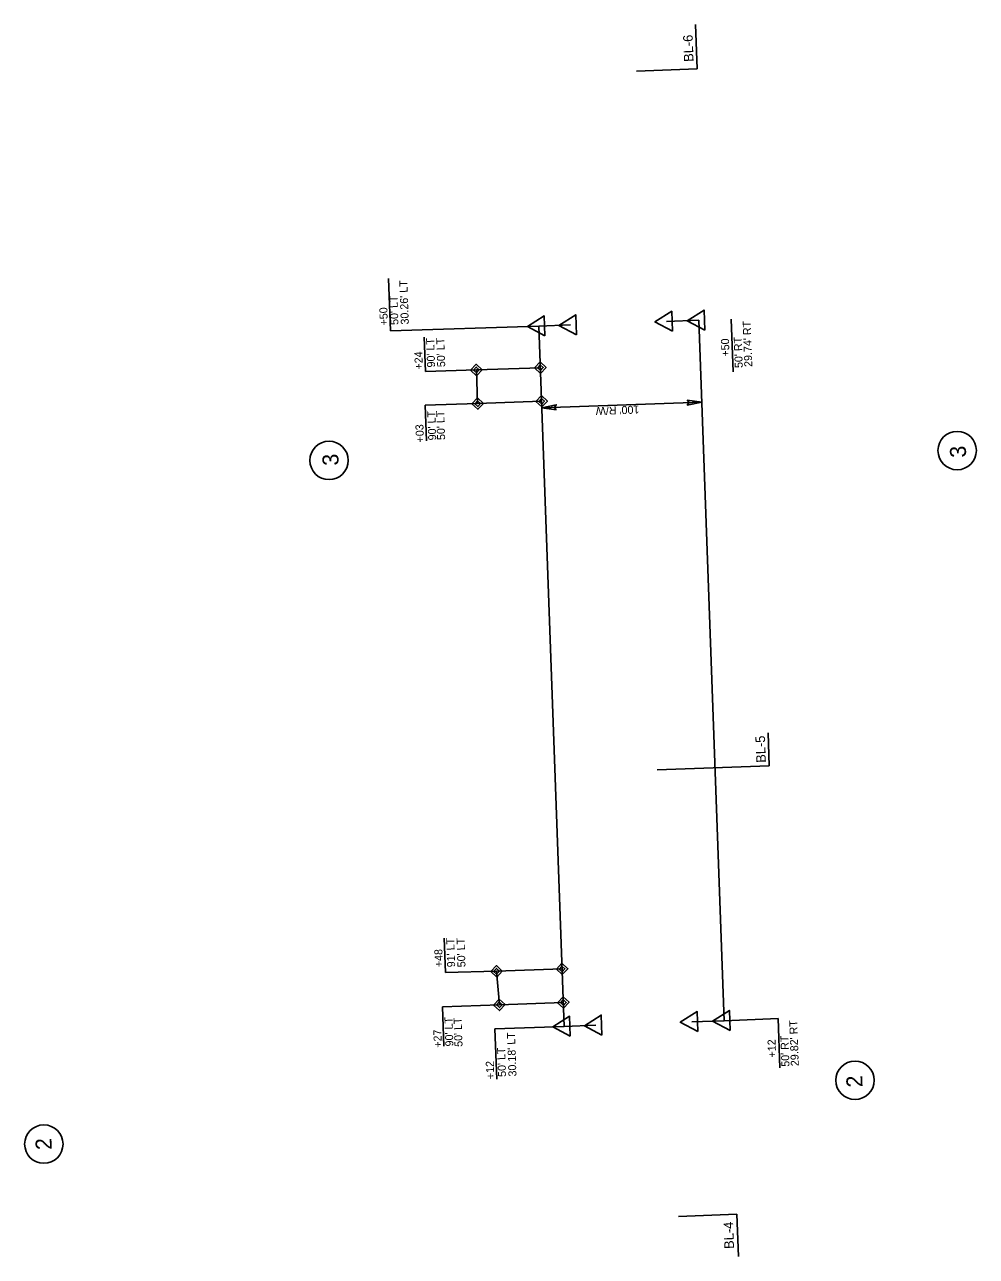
# Model space of a CAD drawing. Extents: x 2065634 to 2066229, y 144790 to 146885.
# Drawn here: x 2065634 to 2066229, y 146115 to 146885 of the extents above; entities that cross this region are included whole.
import ezdxf

# ---------------------------------------------------------------- set-up
doc = ezdxf.new("R2010")
doc.units = 0
for name, color, linetype in [('Prop Dimension', 7, 'Continuous'), ('Prop DSN Text', 7, 'Continuous'), ('Prop Easement Permanent Utility', 7, 'Continuous'), ('Prop Easement Permanent Utility Station Offsets', 7, 'Continuous'), ('Prop Parcel Number CELL', 7, 'Continuous'), ('Prop Parcel Number Text', 7, 'Continuous'), ('Prop ROW Marker CELL', 7, 'Continuous'), ('Prop ROW Permanent Easement CELL', 7, 'Continuous'), ('Prop ROW RW Lines', 7, 'Continuous'), ('Prop ROW Station Offsets', 7, 'Continuous'), ('Prop Terminator CELL', 7, 'Continuous')]:
    doc.layers.add(name, color=color, linetype=linetype)

msp = doc.modelspace()

# ---------------------------------------------------------------- linework, layer by layer
at = {"layer": 'Prop Dimension'}
msp.add_line((2065956.94, 146645), (2066056.88, 146648.61), dxfattribs=at)
at = {"layer": 'Prop DSN Text'}
for p, q in [((2066054.02, 146856.81), (2066053.02, 146884.51)), ((2066016.15, 146855.44), (2066054.02, 146856.81)), ((2066099.13, 146421.28), (2066098.39, 146441.8)), ((2066029.08, 146418.75), (2066099.13, 146421.28)), ((2066042.47, 146139.68), (2066078.89, 146141)), ((2066078.89, 146141), (2066079.84, 146114.71))]:
    msp.add_line(p, q, dxfattribs=at)
at = {"layer": 'Prop Easement Permanent Utility'}
for p, q in [((2065916.06, 146668.68), (2065956.03, 146670.12)), ((2065916.82, 146647.69), (2065916.06, 146668.68)), ((2065916.82, 146647.69), (2065956.79, 146649.13)), ((2065928.64, 146292.88), (2065969.62, 146294.37)), ((2065930.4, 146271.93), (2065928.64, 146292.88)), ((2065930.4, 146271.93), (2065970.38, 146273.38))]:
    msp.add_line(p, q, dxfattribs=at)
at = {"layer": 'Prop Easement Permanent Utility Station Offsets'}
for p, q in [((2065883.39, 146689.17), (2065884.16, 146667.7)), ((2065916.06, 146668.68), (2065884.16, 146667.7)), ((2065916.82, 146647.69), (2065884.01, 146646.66)), ((2065884.01, 146646.66), (2065884.81, 146624.31)), ((2065895.94, 146313.61), (2065896.72, 146292.05)), ((2065928.64, 146292.88), (2065896.72, 146292.05)), ((2065930.4, 146271.93), (2065894.89, 146270.7)), ((2065894.89, 146270.7), (2065895.78, 146246))]:
    msp.add_line(p, q, dxfattribs=at)
at = {"layer": 'Prop Parcel Number CELL'}
for p, q in [((2066216.55, 146618.33), (2066216.55, 146618.33)), ((2065823.94, 146612.14), (2065823.94, 146612.14)), ((2066152.7, 146224.75), (2066152.7, 146224.75)), ((2065645.68, 146184.86), (2065645.68, 146184.86))]:
    msp.add_line(p, q, dxfattribs=at)
for centre in [(2065823.94, 146612.14), (2066216.55, 146618.33), (2066152.7, 146224.75), (2065645.68, 146184.86)]:
    msp.add_circle(centre, 12, dxfattribs=at)
at = {"layer": 'Prop ROW Marker CELL'}
for p, q in [((2065955.09, 146696.1), (2065955.09, 146696.1)), ((2065974.82, 146696.82), (2065974.82, 146696.82)), ((2066034.78, 146698.98), (2066034.78, 146698.98)), ((2066055.03, 146699.72), (2066055.03, 146699.72)), ((2065970.92, 146258.39), (2065970.92, 146258.39)), ((2065990.72, 146259.11), (2065990.72, 146259.11)), ((2066050.68, 146261.27), (2066050.68, 146261.27)), ((2066070.85, 146262), (2066070.85, 146262))]:
    msp.add_line(p, q, dxfattribs=at)
for points in [[(2065958.92, 146689.99), (2065947.9, 146695.84), (2065958.47, 146702.48)], [(2065978.65, 146690.7), (2065967.63, 146696.56), (2065978.19, 146703.19)], [(2066038.61, 146692.87), (2066027.59, 146698.72), (2066038.15, 146705.36)], [(2066058.85, 146693.6), (2066047.83, 146699.46), (2066058.4, 146706.09)], [(2065974.74, 146252.27), (2065963.72, 146258.13), (2065974.29, 146264.77)], [(2065994.55, 146252.99), (2065983.53, 146258.85), (2065994.09, 146265.48)], [(2066054.51, 146255.16), (2066043.49, 146261.01), (2066054.06, 146267.65)], [(2066074.68, 146255.89), (2066063.66, 146261.74), (2066074.22, 146268.38)]]:
    msp.add_lwpolyline(points, close=True, dxfattribs=at)
at = {"layer": 'Prop ROW Permanent Easement CELL'}
for p, q in [((2065916.06, 146668.68), (2065916.06, 146668.68)), ((2065956.03, 146670.12), (2065956.03, 146670.12)), ((2065916.82, 146647.69), (2065916.82, 146647.69)), ((2065956.79, 146649.13), (2065956.79, 146649.13)), ((2065969.62, 146294.37), (2065969.62, 146294.37)), ((2065928.64, 146292.88), (2065928.64, 146292.88)), ((2065930.4, 146271.93), (2065930.4, 146271.93)), ((2065970.38, 146273.38), (2065970.38, 146273.38))]:
    msp.add_line(p, q, dxfattribs=at)
for points in [[(2065919.66, 146668.81), (2065916.19, 146665.08), (2065912.46, 146668.55), (2065915.93, 146672.27)], [(2065917.86, 146668.74), (2065916.12, 146666.88), (2065914.26, 146668.61), (2065915.99, 146670.47)], [(2065956.16, 146666.52), (2065952.44, 146669.99), (2065955.9, 146673.72), (2065959.63, 146670.25)], [(2065956.1, 146668.32), (2065954.23, 146670.06), (2065955.97, 146671.92), (2065957.83, 146670.19)], [(2065913.22, 146647.56), (2065916.69, 146651.29), (2065920.42, 146647.82), (2065916.95, 146644.09)], [(2065915.02, 146647.62), (2065916.75, 146649.49), (2065918.62, 146647.75), (2065916.88, 146645.89)], [(2065956.92, 146645.54), (2065953.19, 146649), (2065956.66, 146652.73), (2065960.39, 146649.26)], [(2065956.86, 146647.34), (2065954.99, 146649.07), (2065956.73, 146650.93), (2065958.59, 146649.2)], [(2065932.24, 146293.01), (2065928.77, 146289.29), (2065925.05, 146292.75), (2065928.51, 146296.48)], [(2065930.44, 146292.95), (2065928.71, 146291.09), (2065926.84, 146292.82), (2065928.58, 146294.68)], [(2065969.75, 146290.77), (2065966.02, 146294.24), (2065969.49, 146297.96), (2065973.21, 146294.5)], [(2065969.68, 146292.57), (2065967.82, 146294.3), (2065969.55, 146296.16), (2065971.42, 146294.43)], [(2065926.8, 146271.8), (2065930.27, 146275.53), (2065934, 146272.06), (2065930.53, 146268.34)], [(2065928.6, 146271.87), (2065930.34, 146273.73), (2065932.2, 146272), (2065930.47, 146270.14)], [(2065970.51, 146269.78), (2065966.78, 146273.25), (2065970.25, 146276.98), (2065973.97, 146273.51)], [(2065970.44, 146271.58), (2065968.58, 146273.31), (2065970.31, 146275.18), (2065972.17, 146273.44)]]:
    msp.add_lwpolyline(points, close=True, dxfattribs=at)
at = {"layer": 'Prop ROW RW Lines'}
for p, q in [((2065955.09, 146696.1), (2065974.82, 146696.82)), ((2065970.92, 146258.39), (2065955.09, 146696.1)), ((2066055.03, 146699.72), (2066034.78, 146698.98)), ((2066070.85, 146262), (2066055.03, 146699.72)), ((2065970.92, 146258.39), (2065990.72, 146259.11)), ((2066050.68, 146261.27), (2066070.85, 146262))]:
    msp.add_line(p, q, dxfattribs=at)
at = {"layer": 'Prop ROW Station Offsets'}
for p, q in [((2065861.15, 146725.76), (2065862.33, 146693.15)), ((2065955.09, 146696.1), (2065862.33, 146693.15)), ((2066076.44, 146667.43), (2066075.25, 146700.45)), ((2066070.85, 146262), (2066104.61, 146263.38)), ((2066104.61, 146263.38), (2066105.72, 146232.47)), ((2065970.92, 146258.39), (2065927.58, 146256.84)), ((2065927.58, 146256.84), (2065928.72, 146225.37))]:
    msp.add_line(p, q, dxfattribs=at)
at = {"layer": 'Prop Terminator CELL'}
for points in [[(2066047.83, 146649.84), (2066056.88, 146648.61), (2066047.89, 146646.69), (2066048.98, 146648.33)], [(2065965.99, 146643.78), (2065956.94, 146645), (2065965.93, 146646.93), (2065964.84, 146645.28)]]:
    msp.add_lwpolyline(points, close=True, dxfattribs=at)

# ---------------------------------------------------------------- texts
at = {"layer": 'Prop Dimension'}
msp.add_text("100' R/W", height=5, rotation=182.19846, dxfattribs=at).set_placement((2066017.81, 146646.5))
at = {"layer": 'Prop DSN Text'}
for s, p in [('BL-6', (2066051.8, 146861.35)), ('BL-5', (2066097, 146423.3)), ('BL-4', (2066077.1, 146119.48))]:
    msp.add_text(s, height=6, rotation=92.07024, dxfattribs=at).set_placement(p)
at = {"layer": 'Prop Easement Permanent Utility Station Offsets'}
for s, p in [("90' LT", (2065890.26, 146670.34)), ("50' LT", (2065896.58, 146670.53)), ('+24', (2065882.6, 146669.03)), ("90' LT", (2065890.99, 146624.79)), ("50' LT", (2065896.54, 146624.99)), ('+03', (2065883.32, 146623.47)), ("91' LT", (2065902.79, 146295.46)), ("50' LT", (2065909.26, 146295.47)), ('+48', (2065895.15, 146295.51)), ("90' LT", (2065901.71, 146246.02)), ("50' LT", (2065907.41, 146245.74)), ('+27', (2065894.5, 146245.21))]:
    msp.add_text(s, height=5, rotation=92.07024, dxfattribs=at).set_placement(p)
at = {"layer": 'Prop Parcel Number Text'}
for s, p in [('3', (2066222.19, 146614.05)), ('3', (2065829.99, 146609.05)), ('2', (2066157.43, 146220.49)), ('2', (2065650.67, 146181.4))]:
    msp.add_text(s, height=10, rotation=92.07024, dxfattribs=at).set_placement(p)
at = {"layer": 'Prop ROW Station Offsets'}
for s, p in [("30.26' LT", (2065873.84, 146697.17)), ("50' LT", (2065867.34, 146696.93)), ('+50', (2065860.75, 146696.58)), ("29.74' RT", (2066088.53, 146670.69)), ('+50', (2066074.29, 146677.13)), ("50' RT", (2066082.58, 146670)), ("30.18' LT", (2065941.12, 146227.2)), ("29.82' RT", (2066117.61, 146233.68)), ('+12', (2066103.39, 146239.11)), ("50' RT", (2066111.75, 146233.31)), ("50' LT", (2065934.63, 146226.97)), ('+12', (2065927.26, 146225.6))]:
    msp.add_text(s, height=5, rotation=92.07024, dxfattribs=at).set_placement(p)

doc.saveas('drawing.dxf')
